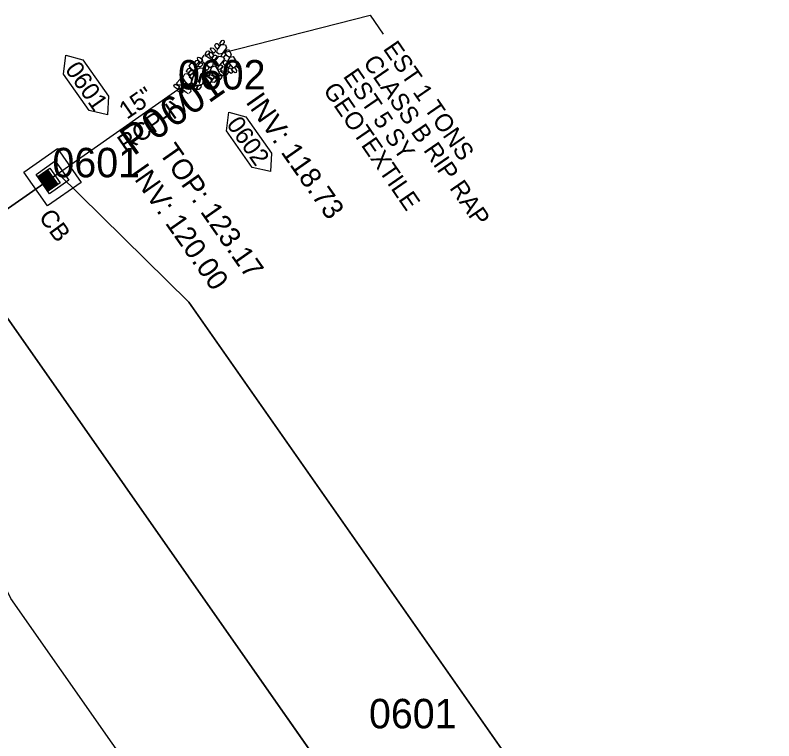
# Model space of a CAD drawing. Extents: x 2296558 to 2299313, y 599200 to 601383.
# Drawn here: x 2297960.1 to 2298088.9, y 600322.8 to 600446 of the extents above; entities that cross this region are included whole.
import ezdxf

# ---------------------------------------------------------------- set-up
doc = ezdxf.new("R2010")
doc.units = 0
for name, color, linetype in [('Prop Drainage Structure Box Number Symbol CELL', 7, 'Continuous'), ('Prop Drainage Structure Catch Basin Grate 840 03F CELL', 7, 'Continuous'), ('Prop Drainage Structure Catch Basin Grate 840 03G Label', 7, 'Continuous'), ('Prop Drainage Structure Pipe RCP 15in Class IV', 7, 'Continuous'), ('Prop Drainage Structure Pipe RCP 15in Class IV Label', 7, 'Continuous'), ('Prop Drainage Structure Plot Symbol 20 Scale', 7, 'Continuous'), ('Prop Drainage Structure Plot Symbol 50 Scale', 7, 'Continuous'), ('Prop Drainage Structure Tops and Inverts LABEL', 7, 'Continuous'), ('Prop Erosion Rip Rap Class B Label', 7, 'Continuous'), ('Prop Erosion Rip Rap Pad at Outlet CELL', 7, 'Continuous'), ('Prop Plan Preparation Watershed Post Construction', 7, 'Continuous'), ('Scratch_Level_1', 7, 'Continuous'), ('Scratch_Level_3', 7, 'Continuous'), ('Scratch_Level_5', 7, 'Continuous')]:
    doc.layers.add(name, color=color, linetype=linetype)

msp = doc.modelspace()

# ---------------------------------------------------------------- linework, layer by layer
at = {"layer": 'Prop Drainage Structure Box Number Symbol CELL'}
for points in [[(2297971.6, 600438.43), (2297975.94, 600432.24), (2297975.77, 600429.11), (2297972.65, 600429.82), (2297968.31, 600436.01), (2297968.69, 600439.21), (2297971.6, 600438.43)], [(2297999.27, 600428.77), (2298003.61, 600422.57), (2298003.43, 600419.45), (2298000.31, 600420.15), (2297995.97, 600426.35), (2297996.36, 600429.54), (2297999.27, 600428.77)]]:
    msp.add_lwpolyline(points, dxfattribs=at)
at = {"layer": 'Prop Drainage Structure Catch Basin Grate 840 03F CELL'}
for p, q in [((2297964.77, 600419.16), (2297964.77, 600419.16)), ((2297964.79, 600417.66), (2297965.03, 600419.15)), ((2297965.16, 600419.13), (2297964.91, 600417.64)), ((2297965.38, 600419.29), (2297965.11, 600417.64)), ((2297965.2, 600417.7), (2297965.49, 600419.47)), ((2297965.42, 600417.86), (2297965.65, 600419.23)), ((2297964.3, 600418.36), (2297964.35, 600418.68)), ((2297964.48, 600418.66), (2297964.43, 600418.34)), ((2297964.46, 600418.13), (2297964.58, 600418.83)), ((2297964.7, 600418.81), (2297964.59, 600418.11)), ((2297964.63, 600417.9), (2297964.81, 600418.99)), ((2297964.93, 600418.97), (2297964.75, 600417.88)), ((2297965.76, 600417.94), (2297965.56, 600416.71)), ((2297965.6, 600416.5), (2297965.85, 600418)), ((2297965.6, 600417.91), (2297965.6, 600417.91)), ((2297965.65, 600418.02), (2297965.81, 600419)), ((2297965.81, 600416.51), (2297966.07, 600418.16)), ((2297965.88, 600418.18), (2297965.97, 600418.77)), ((2297966.03, 600416.67), (2297966.3, 600418.31)), ((2297966.1, 600418.33), (2297966.14, 600418.54)), ((2297966.42, 600418.28), (2297966.16, 600416.65)), ((2297966.26, 600416.83), (2297966.46, 600418.07)), ((2297966.58, 600418.05), (2297966.38, 600416.81)), ((2297966.86, 600418.79), (2297966.86, 600418.79)), ((2297964.82, 600417.36), (2297964.82, 600417.36)), ((2297965.31, 600417.63), (2297965.24, 600417.18)), ((2297966.48, 600416.99), (2297966.62, 600417.84)), ((2297966.49, 600416.71), (2297966.49, 600416.71)), ((2297966.75, 600417.82), (2297966.61, 600416.97)), ((2297966.71, 600417.15), (2297966.79, 600417.61)), ((2297966.91, 600417.59), (2297966.83, 600417.13)), ((2297966.94, 600417.31), (2297966.95, 600417.38)), ((2297967.07, 600417.36), (2297967.06, 600417.29))]:
    msp.add_line(p, q, dxfattribs=at)
for points in [[(2297965.59, 600419.73), (2297967.32, 600417.28), (2297965.68, 600416.13), (2297963.96, 600418.59), (2297966, 600420.02), (2297967.73, 600417.56), (2297967.32, 600417.28)], [(2297967.3, 600417.28), (2297965.68, 600416.14), (2297963.97, 600418.58), (2297965.59, 600419.72), (2297967.3, 600417.28)], [(2297965.61, 600419.48), (2297967.13, 600417.31), (2297965.71, 600416.32), (2297964.15, 600418.55), (2297965.51, 600419.51)], [(2297965.11, 600417.64), (2297964.97, 600417.54), (2297965.26, 600419.31)], [(2297965.61, 600419.45), (2297965.34, 600417.8), (2297965.2, 600417.7)], [(2297965.77, 600419.21), (2297965.57, 600417.96), (2297965.42, 600417.86)], [(2297965.44, 600416.73), (2297965.62, 600417.84), (2297965.76, 600417.94)], [(2297965.93, 600418.98), (2297965.79, 600418.12), (2297965.65, 600418.02)], [(2297965.85, 600418), (2297965.99, 600418.1), (2297965.73, 600416.48)], [(2297966.1, 600418.75), (2297966.02, 600418.28), (2297965.88, 600418.18)], [(2297966.07, 600418.16), (2297966.22, 600418.26), (2297965.93, 600416.49)], [(2297966.26, 600418.52), (2297966.25, 600418.43), (2297966.1, 600418.33)], [(2297965.12, 600417.2), (2297965.17, 600417.53), (2297965.31, 600417.63)], [(2297965.17, 600417.53), (2297965.31, 600417.63), (2297965.24, 600417.18)], [(2297965.28, 600416.97), (2297965.4, 600417.69), (2297965.54, 600417.79), (2297965.4, 600416.95)]]:
    msp.add_lwpolyline(points, dxfattribs=at)
for centre, start, end in [((2297965.09, 600419.14), 350.73, 170.73), ((2297965.32, 600419.3), 350.73, 170.73), ((2297965.55, 600419.46), 350.73, 170.73), ((2297965.71, 600419.22), 350.73, 170.73), ((2297964.36, 600418.35), 170.73, 350.73), ((2297964.42, 600418.67), 350.73, 170.73), ((2297964.53, 600418.12), 170.73, 350.73), ((2297964.64, 600418.82), 350.7293, 170.7293), ((2297964.69, 600417.89), 170.73, 350.73), ((2297964.87, 600418.98), 350.7293, 170.7293), ((2297965.87, 600418.99), 350.73, 170.73), ((2297966.03, 600418.76), 350.73, 170.73), ((2297966.2, 600418.53), 350.73, 170.73), ((2297966.36, 600418.29), 350.73, 170.73), ((2297966.52, 600418.06), 350.73, 170.73), ((2297966.69, 600417.83), 350.73, 170.73), ((2297964.85, 600417.65), 170.73, 350.73), ((2297965.18, 600417.19), 170.73, 350.73), ((2297965.34, 600416.96), 170.73, 350.73), ((2297965.5, 600416.72), 170.73, 350.73), ((2297966.09, 600416.66), 170.73, 350.73), ((2297966.32, 600416.82), 170.73, 350.73), ((2297966.55, 600416.98), 170.73, 350.73), ((2297966.77, 600417.14), 170.73, 350.73), ((2297966.85, 600417.6), 350.73, 170.73), ((2297967, 600417.3), 170.73, 350.73), ((2297967.01, 600417.37), 350.73, 170.73), ((2297965.66, 600416.49), 170.73, 350.73), ((2297965.87, 600416.5), 170.73, 350.73)]:
    msp.add_arc(centre, 0.0625, start, end, dxfattribs=at)
at = {"layer": 'Prop Drainage Structure Pipe RCP 15in Class IV'}
msp.add_line((2297966.86, 600418.79), (2297987.72, 600433.39), dxfattribs=at)
at = {"layer": 'Prop Drainage Structure Plot Symbol 20 Scale'}
msp.add_lwpolyline([(2297965.93, 600415.7), (2297963.64, 600418.97), (2297966.91, 600421.27), (2297969.21, 600417.99)], close=True, dxfattribs=at)
at = {"layer": 'Prop Drainage Structure Plot Symbol 50 Scale'}
msp.add_lwpolyline([(2297965.56, 600413.61), (2297961.55, 600419.34), (2297967.28, 600423.36), (2297971.3, 600417.62)], close=True, dxfattribs=at)
at = {"layer": 'Prop Erosion Rip Rap Class B Label'}
msp.add_lwpolyline([(2297995.3, 600439.61), (2298020.33, 600446.01), (2298022.54, 600442.8)], dxfattribs=at)
at = {"layer": 'Prop Erosion Rip Rap Pad at Outlet CELL'}
msp.add_line((2297987.72, 600433.39), (2297987.72, 600433.39), dxfattribs=at)
msp.add_line((2297987.72, 600433.39), (2297987.72, 600433.39), dxfattribs=at)
for points in [[(2297994.43, 600440.26), (2297994.17, 600440.44), (2297994.01, 600440.84), (2297994.18, 600441.18), (2297994.4, 600441.2), (2297994.75, 600440.72), (2297994.59, 600440.37), (2297994.43, 600440.26)], [(2297994.31, 600439.72), (2297994.46, 600440.2), (2297995.07, 600441.03), (2297995.78, 600440.95), (2297995.99, 600440.45), (2297995.21, 600439.5), (2297994.74, 600439.39), (2297994.25, 600439.67)], [(2297995.58, 600441.66), (2297995.57, 600441.36), (2297995.23, 600440.99), (2297994.92, 600441.03), (2297994.84, 600441.2), (2297995.17, 600441.69), (2297995.37, 600441.74), (2297995.58, 600441.66)], [(2297993.05, 600439.88), (2297993.05, 600439.58), (2297992.71, 600439.21), (2297992.4, 600439.24), (2297992.33, 600439.41), (2297992.65, 600439.9), (2297992.84, 600439.96), (2297993.05, 600439.88)], [(2297993.38, 600440.48), (2297993.71, 600440.4), (2297994.03, 600440.09), (2297994.05, 600439.76), (2297993.81, 600439.58), (2297993.39, 600440.02), (2297993.27, 600440.3), (2297993.38, 600440.48)], [(2297996.34, 600438.85), (2297996.07, 600439.1), (2297995.69, 600439.62), (2297996, 600440.09), (2297996.28, 600440.2), (2297996.74, 600439.38), (2297996.63, 600439.01), (2297996.34, 600438.85)], [(2297991.17, 600438.86), (2297991.43, 600438.82), (2297991.77, 600438.55), (2297991.79, 600438.2), (2297991.53, 600438), (2297991.11, 600438.44), (2297991.02, 600438.74), (2297991.17, 600438.86)], [(2297992.27, 600439.14), (2297992.76, 600438.92), (2297993.77, 600438.3), (2297993.57, 600437.37), (2297993.18, 600437.08), (2297992, 600437.98), (2297991.82, 600438.72), (2297992.19, 600439.24)], [(2297993.44, 600438.77), (2297993.17, 600438.95), (2297993.01, 600439.34), (2297993.18, 600439.7), (2297993.39, 600439.72), (2297993.75, 600439.23), (2297993.6, 600438.88), (2297993.44, 600438.77)], [(2297994.31, 600439.12), (2297994.29, 600438.88), (2297993.95, 600438.43), (2297993.63, 600438.48), (2297993.56, 600438.66), (2297993.9, 600439.19), (2297994.09, 600439.24), (2297994.31, 600439.12)], [(2297993.8, 600437.82), (2297994.02, 600438.21), (2297994.67, 600439.05), (2297995.34, 600438.94), (2297995.65, 600438.52), (2297994.84, 600437.6), (2297994.26, 600437.36), (2297993.9, 600437.75)], [(2297995.81, 600439.56), (2297995.78, 600439.27), (2297995.46, 600438.88), (2297995.15, 600438.93), (2297995.04, 600439.09), (2297995.4, 600439.62), (2297995.64, 600439.67), (2297995.81, 600439.56)], [(2297997.17, 600437.03), (2297996.8, 600437.4), (2297996.2, 600438.17), (2297996.57, 600438.87), (2297997.09, 600438.98), (2297997.73, 600437.96), (2297997.59, 600437.34), (2297997.17, 600437.03)], [(2297990.34, 600436.58), (2297990.01, 600436.84), (2297989.65, 600437.33), (2297989.93, 600437.81), (2297990.28, 600437.87), (2297990.71, 600437.12), (2297990.57, 600436.75), (2297990.34, 600436.58)], [(2297991.24, 600438.28), (2297991.21, 600437.99), (2297990.88, 600437.62), (2297990.58, 600437.65), (2297990.5, 600437.83), (2297990.83, 600438.32), (2297991.03, 600438.37), (2297991.24, 600438.28)], [(2297991.92, 600437.83), (2297991.88, 600437.56), (2297991.54, 600437.22), (2297991.24, 600437.23), (2297991.11, 600437.42), (2297991.5, 600437.91), (2297991.72, 600437.92), (2297991.92, 600437.83)], [(2297992.65, 600436.62), (2297992.38, 600436.79), (2297992.22, 600437.19), (2297992.38, 600437.54), (2297992.6, 600437.56), (2297992.95, 600437.07), (2297992.8, 600436.72), (2297992.65, 600436.62)], [(2297994.13, 600435.4), (2297993.74, 600435.76), (2297993.22, 600436.63), (2297993.53, 600437.23), (2297994.05, 600437.4), (2297994.68, 600436.38), (2297994.59, 600435.66), (2297994.13, 600435.4)], [(2297995.22, 600437.46), (2297995.18, 600437.14), (2297994.85, 600436.77), (2297994.54, 600436.82), (2297994.45, 600436.99), (2297994.79, 600437.48), (2297995.02, 600437.55), (2297995.22, 600437.46)], [(2297995.89, 600437.07), (2297995.78, 600436.9), (2297995.5, 600436.45), (2297995.13, 600436.56), (2297995.03, 600436.71), (2297995.41, 600437.27), (2297995.67, 600437.19), (2297995.89, 600437.07)], [(2297995.66, 600438.34), (2297996, 600438.17), (2297996.52, 600437.67), (2297996.45, 600437.25), (2297996.2, 600437.08), (2297995.54, 600437.61), (2297995.41, 600437.97), (2297995.66, 600438.34)], [(2297998.15, 600436.91), (2297997.91, 600437.11), (2297997.59, 600437.48), (2297997.8, 600437.76), (2297998.05, 600437.86), (2297998.36, 600437.31), (2297998.32, 600437), (2297998.15, 600436.91)], [(2297989.52, 600434.2), (2297989.14, 600434.53), (2297988.54, 600435.34), (2297988.88, 600436.02), (2297989.33, 600436.11), (2297990, 600435.07), (2297989.9, 600434.49), (2297989.52, 600434.2)], [(2297989.89, 600436.94), (2297989.88, 600436.65), (2297989.55, 600436.28), (2297989.23, 600436.31), (2297989.15, 600436.49), (2297989.5, 600436.97), (2297989.69, 600437.03), (2297989.89, 600436.94)], [(2297990.33, 600436.55), (2297990.28, 600436.24), (2297989.93, 600435.9), (2297989.64, 600435.91), (2297989.51, 600436.09), (2297989.91, 600436.62), (2297990.13, 600436.64), (2297990.33, 600436.55)], [(2297990.43, 600435.97), (2297990.42, 600435.68), (2297990.09, 600435.31), (2297989.78, 600435.34), (2297989.7, 600435.51), (2297990.04, 600436.01), (2297990.24, 600436.06), (2297990.43, 600435.97)], [(2297992.38, 600436.76), (2297992.4, 600435.91), (2297991.86, 600434.25), (2297990.68, 600434.03), (2297990.02, 600434.53), (2297990.63, 600436.61), (2297991.48, 600437.08), (2297992.42, 600436.93)], [(2297993.2, 600436.39), (2297993.2, 600436.12), (2297992.84, 600435.76), (2297992.55, 600435.77), (2297992.43, 600435.96), (2297992.79, 600436.47), (2297993.03, 600436.5), (2297993.2, 600436.39)], [(2297993.21, 600435.95), (2297993.42, 600435.84), (2297993.87, 600435.57), (2297993.72, 600435.22), (2297993.59, 600435.12), (2297993.05, 600435.48), (2297993.02, 600435.69), (2297993.21, 600435.95)], [(2297994.89, 600436.58), (2297995.07, 600436.45), (2297995.44, 600436.12), (2297995.4, 600435.81), (2297995.28, 600435.71), (2297994.81, 600435.98), (2297994.73, 600436.29), (2297994.82, 600436.49)], [(2297996.28, 600436.47), (2297996.18, 600436.16), (2297995.86, 600435.75), (2297995.58, 600435.83), (2297995.48, 600435.97), (2297995.83, 600436.52), (2297996.08, 600436.56), (2297996.28, 600436.47)], [(2297996.74, 600436.11), (2297996.49, 600436.3), (2297996.17, 600436.67), (2297996.38, 600436.96), (2297996.63, 600437.05), (2297996.95, 600436.5), (2297996.9, 600436.19), (2297996.74, 600436.11)], [(2297997.42, 600436.21), (2297997.18, 600436.4), (2297996.86, 600436.77), (2297997.07, 600437.06), (2297997.32, 600437.16), (2297997.64, 600436.6), (2297997.59, 600436.29), (2297997.42, 600436.21)], [(2297988.76, 600434.98), (2297988.62, 600434.65), (2297988.28, 600434.12), (2297987.74, 600434.15), (2297987.5, 600434.47), (2297988.11, 600435.16), (2297988.47, 600435.18), (2297988.76, 600434.98)], [(2297992.53, 600433.93), (2297992.29, 600434.12), (2297991.97, 600434.49), (2297992.18, 600434.78), (2297992.43, 600434.88), (2297992.75, 600434.32), (2297992.7, 600434.01), (2297992.53, 600433.93)], [(2297993.17, 600434.52), (2297992.82, 600434.63), (2297992.26, 600435.06), (2297992.31, 600435.51), (2297992.56, 600435.68), (2297993.29, 600435.2), (2297993.36, 600434.78), (2297993.17, 600434.52)], [(2297994.2, 600435.25), (2297994.19, 600434.96), (2297993.86, 600434.58), (2297993.55, 600434.64), (2297993.44, 600434.79), (2297993.79, 600435.32), (2297994.03, 600435.36), (2297994.2, 600435.25)], [(2297995.15, 600435.68), (2297995.14, 600435.4), (2297994.81, 600435.02), (2297994.5, 600435.07), (2297994.39, 600435.22), (2297994.73, 600435.76), (2297994.98, 600435.79), (2297995.15, 600435.68)], [(2297987.26, 600434.31), (2297987.46, 600434.17), (2297987.96, 600433.88), (2297987.8, 600433.59), (2297987.65, 600433.47), (2297987.12, 600433.79), (2297987.02, 600434.13), (2297987.26, 600434.31)], [(2297987.97, 600433.57), (2297988.15, 600433.43), (2297988.62, 600433.17), (2297988.5, 600432.84), (2297988.35, 600432.74), (2297987.77, 600433.06), (2297987.72, 600433.39), (2297987.97, 600433.57)], [(2297989.52, 600432.67), (2297989.14, 600432.89), (2297988.31, 600433.5), (2297988.39, 600434.22), (2297988.86, 600434.49), (2297989.79, 600433.7), (2297989.89, 600433.07), (2297989.62, 600432.74)], [(2297990.06, 600433.47), (2297989.92, 600433.65), (2297989.65, 600434.01), (2297989.82, 600434.29), (2297989.98, 600434.4), (2297990.33, 600433.91), (2297990.33, 600433.54), (2297990.06, 600433.47)], [(2297990.97, 600433.93), (2297990.96, 600433.65), (2297990.63, 600433.27), (2297990.32, 600433.32), (2297990.21, 600433.47), (2297990.56, 600434), (2297990.8, 600434.04), (2297990.97, 600433.93)], [(2297991.69, 600434.05), (2297991.62, 600433.76), (2297991.29, 600433.37), (2297991, 600433.4), (2297990.87, 600433.58), (2297991.26, 600434.11), (2297991.49, 600434.14), (2297991.69, 600434.05)]]:
    msp.add_lwpolyline(points, dxfattribs=at)
at = {"layer": 'Prop Plan Preparation Watershed Post Construction'}
for p, q in [((2297950.04, 600407.01), (2297967.38, 600419.15)), ((2297967.38, 600419.15), (2297989.58, 600397.25)), ((2298066.92, 600240.1), (2297950.04, 600407.01)), ((2297989.58, 600397.25), (2298088.87, 600255.46))]:
    msp.add_line(p, q, dxfattribs=at)
msp.add_lwpolyline([(2297958.64, 600394.72), (2298066.92, 600240.1), (2298044.98, 600224.73), (2297959.37, 600346.97), (2297941.85, 600382.96)], dxfattribs=at)
at = {"layer": 'Scratch_Level_5'}
for p, q in [((2297967.38, 600419.15), (2297950.04, 600407.01)), ((2297989.58, 600397.25), (2297967.38, 600419.15)), ((2297950.04, 600407.01), (2298066.92, 600240.1)), ((2298088.87, 600255.46), (2297989.58, 600397.25))]:
    msp.add_line(p, q, dxfattribs=at)

# ---------------------------------------------------------------- texts
at = {"layer": 'Prop Drainage Structure Box Number Symbol CELL'}
for s, p in [('0601', (2297968.45, 600436.78)), ('0602', (2297995.86, 600427.47))]:
    msp.add_text(s, height=3, rotation=305.0118, dxfattribs=at).set_placement(p)
at = {"layer": 'Prop Drainage Structure Catch Basin Grate 840 03G Label'}
msp.add_text('CB', height=3, rotation=306.1596, dxfattribs=at).set_placement((2297963.98, 600411.72))
at = {"layer": 'Prop Drainage Structure Pipe RCP 15in Class IV Label'}
for s, p in [('15" ', (2297979.06, 600428.22)), ('RCP-IV ', (2297978.81, 600422.57))]:
    msp.add_text(s, height=3, rotation=34.7221, dxfattribs=at).set_placement(p)
at = {"layer": 'Prop Drainage Structure Tops and Inverts LABEL'}
for s, p in [('INV: 118.73', (2297999.12, 600431.28)), ('TOP: 123.17', (2297984.4, 600422.66)), ('INV: 120.00', (2297979.49, 600419.22))]:
    msp.add_text(s, height=3.5, rotation=305.0028, dxfattribs=at).set_placement(p)
at = {"layer": 'Prop Erosion Rip Rap Class B Label'}
for s, p in [('EST 1 TONS', (2298022.44, 600440.3)), ('CLASS B RIP RAP', (2298019.05, 600437.97)), ('EST 5 SY', (2298015.66, 600435.63)), ('GEOTEXTILE', (2298012.27, 600433.3))]:
    msp.add_text(s, height=3, rotation=304.5541, dxfattribs=at).set_placement(p)
at = {"layer": 'Scratch_Level_1'}
msp.add_text('0601', height=5, dxfattribs=at).set_placement((2298020.15, 600324.92))
at = {"layer": 'Scratch_Level_3'}
msp.add_text('P0601', height=5, rotation=35.0027, dxfattribs=at).set_placement((2297980.16, 600422))
at = {"layer": 'Scratch_Level_5'}
for s, p in [('0602', (2297987.72, 600433.39)), ('0601', (2297966.42, 600418.48))]:
    msp.add_text(s, height=5, dxfattribs=at).set_placement(p)

doc.saveas('drawing.dxf')
